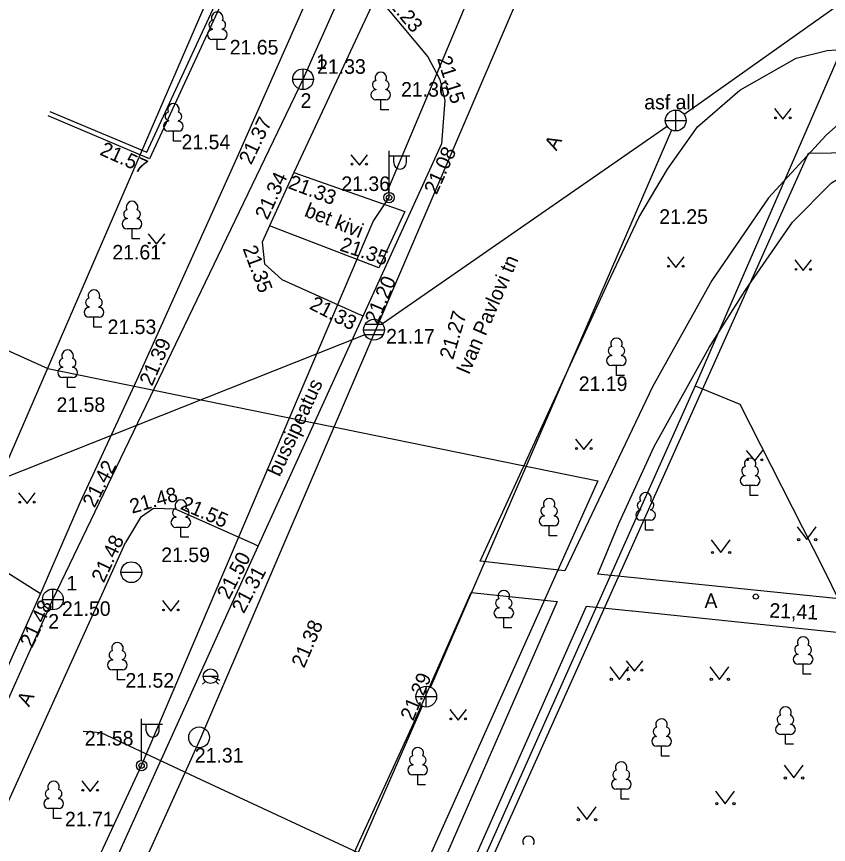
# Model space of a CAD drawing. Extents: x 714391 to 714584, y 6589993 to 6590151.
# Drawn here: x 714417.68 to 714456.74, y 6590052.39 to 6590092.2 of the extents above; entities that cross this region are included whole.
import ezdxf

# ---------------------------------------------------------------- set-up
doc = ezdxf.new("R2010")
doc.units = 0
for name, color, linetype in [('ABIJOONIS', 7, 'Continuous'), ('AED', 7, 'Continuous'), ('HALJASTUS', 7, 'Continuous'), ('HOONE', 7, 'Continuous'), ('KKAEV', 7, 'Continuous'), ('KORGUS', 7, 'Continuous'), ('KPKAABEL', 7, 'Continuous'), ('KTRASS', 7, 'Continuous'), ('MPKAABEL', 7, 'Continuous'), ('POST', 7, 'Continuous'), ('PUU', 7, 'Continuous'), ('RAJATIS', 7, 'Continuous'), ('SITRASS', 7, 'Continuous'), ('SKKAEV', 7, 'Continuous'), ('SKTRASS', 7, 'Continuous'), ('TEE', 7, 'Continuous'), ('TORU NR', 7, 'Continuous'), ('VKAEV', 7, 'Continuous'), ('VTRASS', 7, 'Continuous'), ('Слой 1', 7, 'Continuous')]:
    doc.layers.add(name, color=color, linetype=linetype)

msp = doc.modelspace()

# ---------------------------------------------------------------- linework, layer by layer
at = {"layer": 'ABIJOONIS'}
msp.add_lwpolyline([(714426.529, 6590057.51), (714423.049, 6590049.81), (714418.429, 6590039.54), (714417.917, 6590038.38)], dxfattribs=at)
msp.add_circle((714426.46, 6590057.54), 0.5, dxfattribs=at)
at = {"layer": 'AED'}
msp.add_lwpolyline([(714419.286, 6590087.641), (714423.948, 6590085.67), (714429.409, 6590097.501), (714429.636, 6590097.396), (714424.08, 6590085.358), (714419.194, 6590087.423)], dxfattribs=at)
at = {"layer": 'HALJASTUS'}
for p, q in [((714454.141, 6590087.775), (714454.546, 6590087.27)), ((714454.546, 6590087.27), (714454.941, 6590087.775)), ((714433.765, 6590085.551), (714434.17, 6590085.046)), ((714434.17, 6590085.046), (714434.565, 6590085.551)), ((714424.012, 6590081.758), (714424.417, 6590081.253)), ((714424.417, 6590081.253), (714424.812, 6590081.758)), ((714448.993, 6590080.641), (714449.398, 6590080.136)), ((714449.398, 6590080.136), (714449.793, 6590080.641)), ((714455.123, 6590080.494), (714455.528, 6590079.989)), ((714455.528, 6590079.989), (714455.923, 6590080.494)), ((714444.568, 6590071.881), (714444.973, 6590071.376)), ((714444.973, 6590071.376), (714445.368, 6590071.881)), ((714452.786, 6590071.339), (714453.191, 6590070.834)), ((714453.191, 6590070.834), (714453.586, 6590071.339)), ((714417.781, 6590069.296), (714418.186, 6590068.791)), ((714418.186, 6590068.791), (714418.581, 6590069.296)), ((714455.237, 6590067.657), (714455.7, 6590067.05)), ((714455.7, 6590067.05), (714456.146, 6590067.657)), ((714451.097, 6590067.037), (714451.56, 6590066.43)), ((714451.56, 6590066.43), (714452.006, 6590067.037)), ((714424.701, 6590064.115), (714425.106, 6590063.61)), ((714425.106, 6590063.61), (714425.501, 6590064.115)), ((714447.007, 6590061.225), (714447.412, 6590060.72)), ((714447.412, 6590060.72), (714447.807, 6590061.225)), ((714446.227, 6590060.937), (714446.69, 6590060.33)), ((714446.69, 6590060.33), (714447.136, 6590060.937)), ((714451.037, 6590060.937), (714451.5, 6590060.33)), ((714451.5, 6590060.33), (714451.946, 6590060.937)), ((714438.518, 6590058.877), (714438.923, 6590058.372)), ((714438.923, 6590058.372), (714439.318, 6590058.877)), ((714454.607, 6590056.197), (714455.07, 6590055.59)), ((714455.07, 6590055.59), (714455.516, 6590056.197)), ((714420.818, 6590055.445), (714421.223, 6590054.94)), ((714421.223, 6590054.94), (714421.618, 6590055.445)), ((714451.307, 6590054.957), (714451.77, 6590054.35)), ((714451.77, 6590054.35), (714452.216, 6590054.957)), ((714444.647, 6590054.197), (714445.11, 6590053.59)), ((714445.11, 6590053.59), (714445.556, 6590054.197))]:
    msp.add_line(p, q, dxfattribs=at)
for centre, radius in [((714454.193, 6590087.325), 0.0428), ((714454.893, 6590087.325), 0.0452), ((714433.817, 6590085.102), 0.0428), ((714434.517, 6590085.102), 0.0452), ((714424.064, 6590081.309), 0.0428), ((714424.764, 6590081.309), 0.0452), ((714449.045, 6590080.191), 0.0428), ((714449.745, 6590080.191), 0.0452), ((714455.175, 6590080.044), 0.0428), ((714455.875, 6590080.044), 0.0452), ((714444.62, 6590071.431), 0.0428), ((714445.32, 6590071.431), 0.0452), ((714452.838, 6590070.89), 0.0428), ((714453.538, 6590070.89), 0.0452), ((714417.833, 6590068.846), 0.0428), ((714418.533, 6590068.846), 0.0452), ((714455.299, 6590067.05), 0.055), ((714456.128, 6590067.05), 0.055), ((714451.159, 6590066.43), 0.055), ((714451.988, 6590066.43), 0.055), ((714424.753, 6590063.665), 0.0428), ((714425.453, 6590063.665), 0.0452), ((714447.059, 6590060.775), 0.0428), ((714447.759, 6590060.775), 0.0452), ((714446.289, 6590060.33), 0.055), ((714447.118, 6590060.33), 0.055), ((714451.099, 6590060.33), 0.055), ((714451.928, 6590060.33), 0.055), ((714438.57, 6590058.427), 0.0428), ((714439.27, 6590058.427), 0.0452), ((714454.669, 6590055.59), 0.055), ((714455.498, 6590055.59), 0.055), ((714420.87, 6590054.996), 0.0428), ((714421.57, 6590054.996), 0.0452), ((714451.369, 6590054.35), 0.055), ((714452.198, 6590054.35), 0.055), ((714444.709, 6590053.59), 0.055), ((714445.538, 6590053.59), 0.055)]:
    msp.add_circle(centre, radius, dxfattribs=at)
at = {"layer": 'HOONE'}
for points in [[(714459.73, 6590096.05), (714450.33, 6590074.44), (714440.46, 6590052.39), (714432.7, 6590035.24), (714421.56, 6590009.98), (714417.1, 6590000.12), (714413.783, 6589992.711)], [(714450.33, 6590074.44), (714452.482, 6590073.562), (714456.5, 6590065.64), (714458.03, 6590062.54), (714457.37, 6590048.6), (714456.96, 6590042.47)]]:
    msp.add_lwpolyline(points, dxfattribs=at)
at = {"layer": 'KKAEV'}
for p, q in [((714431.463, 6590088.686), (714431.463, 6590089.686)), ((714430.963, 6590089.186), (714431.963, 6590089.186)), ((714449.39, 6590086.7), (714449.39, 6590087.7)), ((714448.89, 6590087.2), (714449.89, 6590087.2)), ((714419.428, 6590063.672), (714419.428, 6590064.672)), ((714418.928, 6590064.172), (714419.928, 6590064.172)), ((714437.39, 6590059), (714437.39, 6590060)), ((714436.89, 6590059.5), (714437.89, 6590059.5))]:
    msp.add_line(p, q, dxfattribs=at)
for centre in [(714431.463, 6590089.186), (714449.39, 6590087.2), (714419.428, 6590064.172), (714437.39, 6590059.5)]:
    msp.add_circle(centre, 0.5, dxfattribs=at)
at = {"layer": 'KORGUS'}
msp.add_circle((714453.24, 6590064.31), 0.125, dxfattribs=at)
at = {"layer": 'KPKAABEL'}
msp.add_lwpolyline([(714390.649, 6590090.709), (714391.22, 6590087.72), (714411.651, 6590078.699), (714417.543, 6590076.021), (714419.18, 6590075.27), (714445.64, 6590069.88), (714433.16, 6590042.04), (714420.76, 6590014.4), (714410.92, 6589992.711)], dxfattribs=at)
at = {"layer": 'KTRASS'}
for p, q in [((714431.463, 6590089.186), (714438.594, 6590105.207)), ((714419.428, 6590064.172), (714431.463, 6590089.186)), ((714409.68, 6590042.435), (714419.428, 6590064.172))]:
    msp.add_line(p, q, dxfattribs=at)
at = {"layer": 'MPKAABEL'}
msp.add_lwpolyline([(714394.611, 6589992.711), (714400.19, 6590004.938), (714412.114, 6590031.265), (714423.696, 6590056.183), (714434.84, 6590082.35), (714435.599, 6590083.495), (714435.59, 6590083.97), (714441.1, 6590097.08), (714442.02, 6590098.72), (714442.75, 6590099.35), (714444.22, 6590100.41), (714445.54, 6590101.3), (714446.63, 6590102.41), (714450.168, 6590111.053), (714453.153, 6590116.846), (714463.66, 6590139.57), (714466.53, 6590147), (714468.444, 6590151.075)], dxfattribs=at)
at = {"layer": 'POST'}
for p, q in [((714435.599, 6590083.745), (714435.599, 6590085.745)), ((714435.599, 6590085.495), (714436.599, 6590085.495)), ((714435.826, 6590085.174), (714435.826, 6590085.495)), ((714436.438, 6590085.174), (714436.438, 6590085.495)), ((714435.599, 6590083.495), (714435.599, 6590083.495)), ((714423.696, 6590056.433), (714423.696, 6590058.433)), ((714423.696, 6590058.183), (714424.696, 6590058.183)), ((714423.923, 6590057.862), (714423.923, 6590058.183)), ((714424.535, 6590057.862), (714424.535, 6590058.183)), ((714423.696, 6590056.183), (714423.696, 6590056.183))]:
    msp.add_line(p, q, dxfattribs=at)
for centre, radius in [((714435.599, 6590083.495), 0.25), ((714435.599, 6590083.495), 0.127), ((714423.696, 6590056.183), 0.25), ((714423.696, 6590056.183), 0.127)]:
    msp.add_circle(centre, radius, dxfattribs=at)
for centre in [(714436.132, 6590085.174), (714424.229, 6590057.862)]:
    msp.add_arc(centre, 0.306, 180, 0, dxfattribs=at)
at = {"layer": 'PUU'}
for p, q in [((714427.097, 6590091.6), (714427.097, 6590091.57)), ((714427.577, 6590091.6), (714427.577, 6590091.57)), ((714427.577, 6590091.095), (714427.097, 6590091.095)), ((714427.337, 6590090.62), (714427.337, 6590091.095)), ((714427.717, 6590090.62), (714427.337, 6590090.62)), ((714434.962, 6590088.701), (714434.962, 6590088.671)), ((714435.442, 6590088.701), (714435.442, 6590088.671)), ((714435.442, 6590088.196), (714434.962, 6590088.196)), ((714435.202, 6590087.721), (714435.202, 6590088.196)), ((714435.582, 6590087.721), (714435.202, 6590087.721)), ((714424.985, 6590087.193), (714424.985, 6590087.163)), ((714425.465, 6590087.193), (714425.465, 6590087.163)), ((714425.465, 6590086.688), (714424.985, 6590086.688)), ((714425.225, 6590086.213), (714425.225, 6590086.688)), ((714425.605, 6590086.213), (714425.225, 6590086.213)), ((714422.995, 6590082.498), (714422.995, 6590082.468)), ((714423.475, 6590082.498), (714423.475, 6590082.468)), ((714423.475, 6590081.993), (714422.995, 6590081.993)), ((714423.235, 6590081.518), (714423.235, 6590081.993)), ((714423.615, 6590081.518), (714423.235, 6590081.518)), ((714421.164, 6590078.246), (714421.164, 6590078.216)), ((714421.644, 6590078.246), (714421.644, 6590078.216)), ((714421.644, 6590077.741), (714421.164, 6590077.741)), ((714421.404, 6590077.266), (714421.404, 6590077.741)), ((714421.784, 6590077.266), (714421.404, 6590077.266)), ((714446.3, 6590075.92), (714446.3, 6590075.89)), ((714446.78, 6590075.92), (714446.78, 6590075.89)), ((714419.897, 6590075.35), (714419.897, 6590075.32)), ((714420.377, 6590075.35), (714420.377, 6590075.32)), ((714446.78, 6590075.415), (714446.3, 6590075.415)), ((714446.54, 6590074.94), (714446.54, 6590075.415)), ((714420.377, 6590074.845), (714419.897, 6590074.845)), ((714420.137, 6590074.37), (714420.137, 6590074.845)), ((714446.92, 6590074.94), (714446.54, 6590074.94)), ((714420.517, 6590074.37), (714420.137, 6590074.37)), ((714453.21, 6590069.645), (714452.73, 6590069.645)), ((714452.97, 6590069.17), (714452.97, 6590069.645)), ((714453.35, 6590069.17), (714452.97, 6590069.17)), ((714447.7, 6590068.49), (714447.7, 6590068.46)), ((714448.18, 6590068.49), (714448.18, 6590068.46)), ((714425.344, 6590068.14), (714425.344, 6590068.11)), ((714425.824, 6590068.14), (714425.824, 6590068.11)), ((714443.06, 6590068.21), (714443.06, 6590068.18)), ((714443.54, 6590068.21), (714443.54, 6590068.18)), ((714448.18, 6590067.985), (714447.7, 6590067.985)), ((714447.94, 6590067.51), (714447.94, 6590067.985)), ((714425.824, 6590067.635), (714425.344, 6590067.635)), ((714425.584, 6590067.16), (714425.584, 6590067.635)), ((714443.54, 6590067.705), (714443.06, 6590067.705)), ((714443.3, 6590067.23), (714443.3, 6590067.705)), ((714425.964, 6590067.16), (714425.584, 6590067.16)), ((714443.68, 6590067.23), (714443.3, 6590067.23)), ((714448.32, 6590067.51), (714447.94, 6590067.51)), ((714440.88, 6590063.79), (714440.88, 6590063.76)), ((714441.36, 6590063.79), (714441.36, 6590063.76)), ((714441.36, 6590063.285), (714440.88, 6590063.285)), ((714441.12, 6590062.81), (714441.12, 6590063.285)), ((714441.5, 6590062.81), (714441.12, 6590062.81)), ((714422.291, 6590061.29), (714422.291, 6590061.26)), ((714422.771, 6590061.29), (714422.771, 6590061.26)), ((714422.771, 6590060.785), (714422.291, 6590060.785)), ((714422.531, 6590060.31), (714422.531, 6590060.785)), ((714455.76, 6590061.055), (714455.28, 6590061.055)), ((714455.52, 6590060.58), (714455.52, 6590061.055)), ((714455.9, 6590060.58), (714455.52, 6590060.58)), ((714422.911, 6590060.31), (714422.531, 6590060.31)), ((714454.91, 6590057.685), (714454.43, 6590057.685)), ((714454.67, 6590057.21), (714454.67, 6590057.685)), ((714455.05, 6590057.21), (714454.67, 6590057.21)), ((714448.95, 6590057.115), (714448.47, 6590057.115)), ((714448.71, 6590056.64), (714448.71, 6590057.115)), ((714449.09, 6590056.64), (714448.71, 6590056.64)), ((714436.74, 6590056.24), (714436.74, 6590056.21)), ((714437.22, 6590056.24), (714437.22, 6590056.21)), ((714437.22, 6590055.735), (714436.74, 6590055.735)), ((714436.98, 6590055.26), (714436.98, 6590055.735)), ((714437.36, 6590055.26), (714436.98, 6590055.26)), ((714447.01, 6590055.045), (714446.53, 6590055.045)), ((714446.77, 6590054.57), (714446.77, 6590055.045)), ((714419.223, 6590054.621), (714419.223, 6590054.591)), ((714419.703, 6590054.621), (714419.703, 6590054.591)), ((714447.15, 6590054.57), (714446.77, 6590054.57)), ((714419.703, 6590054.116), (714419.223, 6590054.116)), ((714419.463, 6590053.641), (714419.463, 6590054.116)), ((714419.843, 6590053.641), (714419.463, 6590053.641))]:
    msp.add_line(p, q, dxfattribs=at)
for centre, radius, start, end in [((714427.337, 6590092.14), 0.277, 332.5799, 207.4201), ((714427.147, 6590091.808), 0.212, 105.2441, 257.079), ((714427.527, 6590091.808), 0.212, 282.921, 74.7559), ((714427.1, 6590091.333), 0.237, 90, 270), ((714427.574, 6590091.333), 0.237, 270, 90), ((714435.202, 6590089.241), 0.277, 332.5799, 207.4201), ((714435.012, 6590088.909), 0.212, 105.2441, 257.079), ((714435.392, 6590088.909), 0.212, 282.921, 74.7559), ((714434.965, 6590088.434), 0.237, 90, 270), ((714435.44, 6590088.434), 0.237, 270, 90), ((714425.225, 6590087.733), 0.277, 332.5799, 207.4201), ((714425.035, 6590087.401), 0.212, 105.2441, 257.079), ((714425.415, 6590087.401), 0.212, 282.921, 74.7559), ((714424.987, 6590086.926), 0.237, 90, 270), ((714425.462, 6590086.926), 0.237, 270, 90), ((714423.235, 6590083.038), 0.277, 332.5799, 207.4201), ((714423.045, 6590082.706), 0.212, 105.2441, 257.079), ((714423.425, 6590082.706), 0.212, 282.921, 74.7559), ((714422.997, 6590082.231), 0.237, 90, 270), ((714423.472, 6590082.231), 0.237, 270, 90), ((714421.404, 6590078.786), 0.277, 332.5799, 207.4201), ((714421.214, 6590078.454), 0.212, 105.2441, 257.079), ((714421.594, 6590078.454), 0.212, 282.921, 74.7559), ((714421.166, 6590077.979), 0.237, 90, 270), ((714421.641, 6590077.979), 0.237, 270, 90), ((714446.54, 6590076.46), 0.277, 332.5799, 207.4201), ((714446.35, 6590076.128), 0.212, 105.2441, 257.079), ((714446.73, 6590076.128), 0.212, 282.921, 74.7559), ((714420.137, 6590075.89), 0.277, 332.5799, 207.4201), ((714446.302, 6590075.653), 0.237, 90, 270), ((714446.777, 6590075.653), 0.237, 270, 90), ((714419.947, 6590075.558), 0.212, 105.2441, 257.079), ((714420.327, 6590075.558), 0.212, 282.921, 74.7559), ((714419.899, 6590075.083), 0.237, 90, 270), ((714420.374, 6590075.083), 0.237, 270, 90), ((714452.97, 6590070.69), 0.277, 332.5799, 207.4201), ((714452.8, 6590070.343), 0.233, 109.0217, 253.1415), ((714453.14, 6590070.343), 0.233, 286.8508, 70.9859), ((714452.733, 6590069.882), 0.238, 90.0016, 269.3953), ((714453.207, 6590069.882), 0.238, 270.6047, 89.9984), ((714447.94, 6590069.03), 0.277, 332.5799, 207.4201), ((714425.584, 6590068.68), 0.277, 332.5799, 207.4201), ((714443.3, 6590068.75), 0.277, 332.5799, 207.4201), ((714447.75, 6590068.698), 0.212, 105.2441, 257.079), ((714448.13, 6590068.698), 0.212, 282.921, 74.7559), ((714425.394, 6590068.348), 0.212, 105.2441, 257.079), ((714425.774, 6590068.348), 0.212, 282.921, 74.7559), ((714443.11, 6590068.418), 0.212, 105.2441, 257.079), ((714443.49, 6590068.418), 0.212, 282.921, 74.7559), ((714447.703, 6590068.223), 0.237, 90, 270), ((714448.177, 6590068.223), 0.237, 270, 90), ((714425.346, 6590067.873), 0.237, 90, 270), ((714425.821, 6590067.873), 0.237, 270, 90), ((714443.062, 6590067.943), 0.237, 90, 270), ((714443.537, 6590067.943), 0.237, 270, 90), ((714441.12, 6590064.33), 0.277, 332.5799, 207.4201), ((714440.93, 6590063.998), 0.212, 105.2441, 257.079), ((714441.31, 6590063.998), 0.212, 282.921, 74.7559), ((714440.883, 6590063.522), 0.237, 90, 270), ((714441.358, 6590063.522), 0.237, 270, 90), ((714455.52, 6590062.1), 0.277, 332.5799, 207.4201), ((714422.531, 6590061.83), 0.277, 332.5799, 207.4201), ((714455.35, 6590061.753), 0.233, 109.0217, 253.1415), ((714455.69, 6590061.753), 0.233, 286.8508, 70.9859), ((714422.341, 6590061.498), 0.212, 105.2441, 257.079), ((714422.721, 6590061.498), 0.212, 282.921, 74.7559), ((714422.293, 6590061.022), 0.237, 90, 270), ((714422.769, 6590061.022), 0.237, 270, 90), ((714455.283, 6590061.292), 0.238, 90.0016, 269.3953), ((714455.757, 6590061.292), 0.238, 270.6047, 89.9984), ((714454.67, 6590058.73), 0.277, 332.5799, 207.4201), ((714448.71, 6590058.16), 0.277, 332.5799, 207.4201), ((714454.5, 6590058.383), 0.233, 109.0217, 253.1415), ((714454.84, 6590058.383), 0.233, 286.8508, 70.9859), ((714448.54, 6590057.813), 0.233, 109.0217, 253.1415), ((714448.88, 6590057.813), 0.233, 286.8508, 70.9859), ((714454.433, 6590057.922), 0.238, 90.0016, 269.3953), ((714454.907, 6590057.922), 0.238, 270.6047, 89.9984), ((714448.473, 6590057.352), 0.238, 90.0016, 269.3953), ((714448.947, 6590057.352), 0.238, 270.6047, 89.9984), ((714436.98, 6590056.78), 0.277, 332.5799, 207.4201), ((714436.79, 6590056.448), 0.212, 105.2441, 257.079), ((714437.17, 6590056.448), 0.212, 282.921, 74.7559), ((714436.742, 6590055.973), 0.237, 90, 270), ((714437.217, 6590055.973), 0.237, 270, 90), ((714446.77, 6590056.09), 0.277, 332.5799, 207.4201), ((714446.6, 6590055.743), 0.233, 109.0217, 253.1415), ((714446.94, 6590055.743), 0.233, 286.8508, 70.9859), ((714419.463, 6590055.161), 0.277, 332.5799, 207.4201), ((714446.533, 6590055.282), 0.238, 90.0016, 269.3953), ((714447.007, 6590055.282), 0.238, 270.6047, 89.9984), ((714419.273, 6590054.829), 0.212, 105.2441, 257.079), ((714419.653, 6590054.829), 0.212, 282.921, 74.7559), ((714419.225, 6590054.354), 0.237, 90, 270), ((714419.7, 6590054.354), 0.237, 270, 90), ((714442.31, 6590052.52), 0.277, 332.5799, 207.4201), ((714442.31, 6590052.52), 0.277, 332.5799, 39.5708)]:
    msp.add_arc(centre, radius, start, end, dxfattribs=at)
at = {"layer": 'SITRASS'}
msp.add_line((714428.828, 6590097.575), (714403.181, 6590038.435), dxfattribs=at)
at = {"layer": 'SKKAEV'}
for p, q in [((714434.375, 6590077.141), (714435.375, 6590077.141)), ((714435.305, 6590077.391), (714434.445, 6590077.391)), ((714435.305, 6590076.891), (714434.445, 6590076.891))]:
    msp.add_line(p, q, dxfattribs=at)
msp.add_circle((714434.875, 6590077.141), 0.5, dxfattribs=at)
at = {"layer": 'SKTRASS'}
for p, q in [((714463.282, 6590097.077), (714449.797, 6590087.49)), ((714449.191, 6590086.741), (714437.589, 6590059.959)), ((714437.189, 6590059.042), (714419.801, 6590019.338))]:
    msp.add_line(p, q, dxfattribs=at)
for points in [[(714448.982, 6590086.911), (714435.286, 6590077.426)], [(714434.439, 6590076.889), (714390.649, 6590059.517)]]:
    msp.add_lwpolyline(points, dxfattribs=at)
at = {"layer": 'TEE'}
for points in [[(714390.65, 6590124.59), (714396, 6590120.47), (714402.53, 6590115.27), (714412.65, 6590108.38), (714428.405, 6590098.635), (714430.062, 6590097.596), (714432.277, 6590096.218), (714432.498, 6590094.946), (714428.283, 6590085.404), (714423.452, 6590074.702), (714420.733, 6590068.851), (714418.831, 6590064.457), (714408.849, 6590042.202), (714401.401, 6590025.886)], [(714435, 6590093.228), (714431.011, 6590084.697), (714429.842, 6590082.14)], [(714435, 6590093.228), (714437.473, 6590090.263), (714438.044, 6590089.173), (714438.287, 6590088.162), (714438.124, 6590086.085)], [(714439.98, 6590066.01), (714446.14, 6590079.41), (714447.61, 6590082.54), (714448.99, 6590084.86), (714450.43, 6590086.9), (714452.47, 6590088.66), (714455.19, 6590090.19), (714456.67, 6590090.57), (714457.54, 6590090.63)], [(714457.54, 6590090.63), (714457.51, 6590087.28), (714456.63, 6590086.49), (714453.85, 6590083.48), (714451.12, 6590079.51), (714448.27, 6590074.4), (714444.05, 6590065.54), (714439.98, 6590066.01)], [(714459.34, 6590064.51), (714458.67, 6590064.05), (714447.983, 6590065.15), (714447.715, 6590065.177), (714445.65, 6590065.39), (714446.67, 6590067.85), (714448.36, 6590071.52), (714451, 6590076.28), (714452.73, 6590079.02), (714455.01, 6590082.32), (714456.89, 6590084.2), (714458.87, 6590085.38), (714460.64, 6590085.94), (714462.556, 6590086.069), (714469.16, 6590086.164), (714483.473, 6590086.366), (714493.922, 6590086.42), (714493.109, 6590083.292)], [(714438.124, 6590086.085), (714427.962, 6590063.804), (714421.239, 6590048.97), (714410.72, 6590025.97)], [(714431.011, 6590084.697), (714436.353, 6590082.818), (714435.115, 6590080.118), (714429.842, 6590082.14), (714429.5, 6590081.35), (714429.614, 6590080.305), (714430.449, 6590079.553), (714434.121, 6590077.906), (714434.347, 6590077.804)], [(714408.586, 6590071.058), (714411.386, 6590069.149), (714418.831, 6590064.457)], [(714429.301, 6590066.741), (714429.103, 6590066.829), (714425.322, 6590068.511), (714424.275, 6590068.543), (714423.645, 6590068.12), (714422.922, 6590066.912)], [(714403.962, 6590024.844), (714405.48, 6590028.39), (714415.772, 6590051.14), (714422.922, 6590066.912)], [(714439.555, 6590064.499), (714443.68, 6590064.07), (714435.23, 6590044.74), (714430.917, 6590045.447)], [(714436.708, 6590058.068), (714439.555, 6590064.499)], [(714459.31, 6590061.9), (714458.22, 6590062.47), (714447.303, 6590063.601), (714447.271, 6590063.604), (714445.09, 6590063.83), (714436.59, 6590044.66), (714438.563, 6590044.596), (714438.967, 6590044.582), (714457.41, 6590043.98), (714457.72, 6590044.12), (714458.5, 6590044.49)], [(714406.684, 6589992.711), (714411.807, 6590003.978), (714420.103, 6590022.258), (714430.572, 6590044.696), (714436.708, 6590058.068)]]:
    msp.add_lwpolyline(points, dxfattribs=at)
at = {"layer": 'VKAEV'}
for p, q in [((714422.7, 6590065.48), (714423.7, 6590065.48)), ((714426.665, 6590060.478), (714427.365, 6590060.478)), ((714426.768, 6590060.231), (714426.628, 6590060.091)), ((714427.262, 6590060.231), (714427.402, 6590060.091))]:
    msp.add_line(p, q, dxfattribs=at)
for centre, radius in [((714423.2, 6590065.48), 0.5), ((714427.015, 6590060.478), 0.35)]:
    msp.add_circle(centre, radius, dxfattribs=at)
at = {"layer": 'VTRASS'}
for p, q in [((714442.442, 6590094.595), (714426.529, 6590057.51)), ((714427.015, 6590060.478), (714427.454, 6590060.29))]:
    msp.add_line(p, q, dxfattribs=at)
msp.add_lwpolyline([(714438.948, 6590050.19), (714434.765, 6590051.691), (714426.564, 6590055.491), (714421.748, 6590057.766), (714420.884, 6590057.818)], dxfattribs=at)
at = {"layer": 'Слой 1'}
msp.add_lwpolyline([(714455.78, 6590085.63), (714478.99, 6590085.97), (714478.28, 6590068.22), (714475.39, 6590009.54), (714423.1, 6590012.8)], close=True, dxfattribs=at)

# ---------------------------------------------------------------- texts
at = {"layer": 'KKAEV'}
msp.add_text('asf all', height=0.7, dxfattribs=at).set_placement((714447.875, 6590087.735))
at = {"layer": 'KORGUS'}
for s, rotation, p in [('21.23', 310.0862, (714435.236, 6590093.161)), ('21.15', 287.5799, (714437.903, 6590090.182)), ('21.37', 64.24, (714428.968, 6590085.037)), ('21.57', 335.7061, (714421.641, 6590085.571)), ('21.08', 65.6299, (714437.886, 6590083.602)), ('21.34', 65.1626, (714429.749, 6590082.382)), ('21.33', 339.1874, (714430.7, 6590083.957)), ('21.35', 341.5651, (714433.189, 6590080.957)), ('21.35', 290.4375, (714428.547, 6590081.046)), ('21.20', 67.0362, (714435.043, 6590077.373)), ('21.33', 332.6761, (714431.725, 6590078.168)), ('21.27', 73.548, (714438.677, 6590075.665)), ('21.39', 66.3959, (714424.198, 6590074.395)), ('21.42', 62.8054, (714421.433, 6590068.542)), ('21.48', 15.7595, (714423.236, 6590068.293)), ('21.55', 336.3262, (714425.517, 6590068.534)), ('21.48', 64.7406, (714421.874, 6590064.936)), ('21.50', 62.9044, (714427.901, 6590064.13)), ('21.31', 62.074, (714428.613, 6590063.457)), ('21.48', 64.6223, (714418.434, 6590061.815)), ('21,41', 357.546, (714453.885, 6590063.3)), ('21.38', 66.6595, (714431.512, 6590060.836)), ('21.29', 67.4204, (714436.756, 6590058.296))]:
    msp.add_text(s, height=0.7, rotation=rotation, dxfattribs=at).set_placement(p)
for s, p in [('21.65', (714427.935, 6590090.376)), ('21.33', (714432.138, 6590089.446)), ('21.36', (714436.177, 6590088.346)), ('21.54', (714425.617, 6590085.82)), ('21.36', (714433.304, 6590083.811)), ('21.25', (714448.598, 6590082.23)), ('21.61', (714422.289, 6590080.519)), ('21.53', (714422.059, 6590076.931)), ('21.17', (714435.458, 6590076.478)), ('21.19', (714444.725, 6590074.195)), ('21.58', (714419.603, 6590073.188)), ('21.59', (714424.64, 6590065.968)), ('21.50', (714419.862, 6590063.381)), ('21.52', (714422.919, 6590059.93)), ('21.58', (714420.962, 6590057.147)), ('21.31', (714426.257, 6590056.331)), ('21.71', (714420.009, 6590053.261))]:
    msp.add_text(s, height=0.7, dxfattribs=at).set_placement(p)
at = {"layer": 'RAJATIS'}
msp.add_text('bussipeatus', height=0.7, rotation=65.2788, dxfattribs=at).set_placement((714430.339, 6590070.033))
at = {"layer": 'TEE'}
for s, rotation, p in [('A', 62.8402, (714443.656, 6590085.707)), ('bet kivi', 338.1359, (714431.481, 6590082.617)), ('Ivan Pavlovi tn', 66.74, (714439.44, 6590074.939)), ('A', 62.8402, (714418.279, 6590058.976))]:
    msp.add_text(s, height=0.7, rotation=rotation, dxfattribs=at).set_placement(p)
msp.add_text('A', height=0.7, dxfattribs=at).set_placement((714450.774, 6590063.76))
at = {"layer": 'TORU NR'}
for s, p in [('1', (714432.085, 6590089.677)), ('2', (714431.343, 6590087.809)), ('1', (714420.075, 6590064.606)), ('2', (714419.205, 6590062.77))]:
    msp.add_text(s, height=0.7, dxfattribs=at).set_placement(p)

doc.saveas('drawing.dxf')
